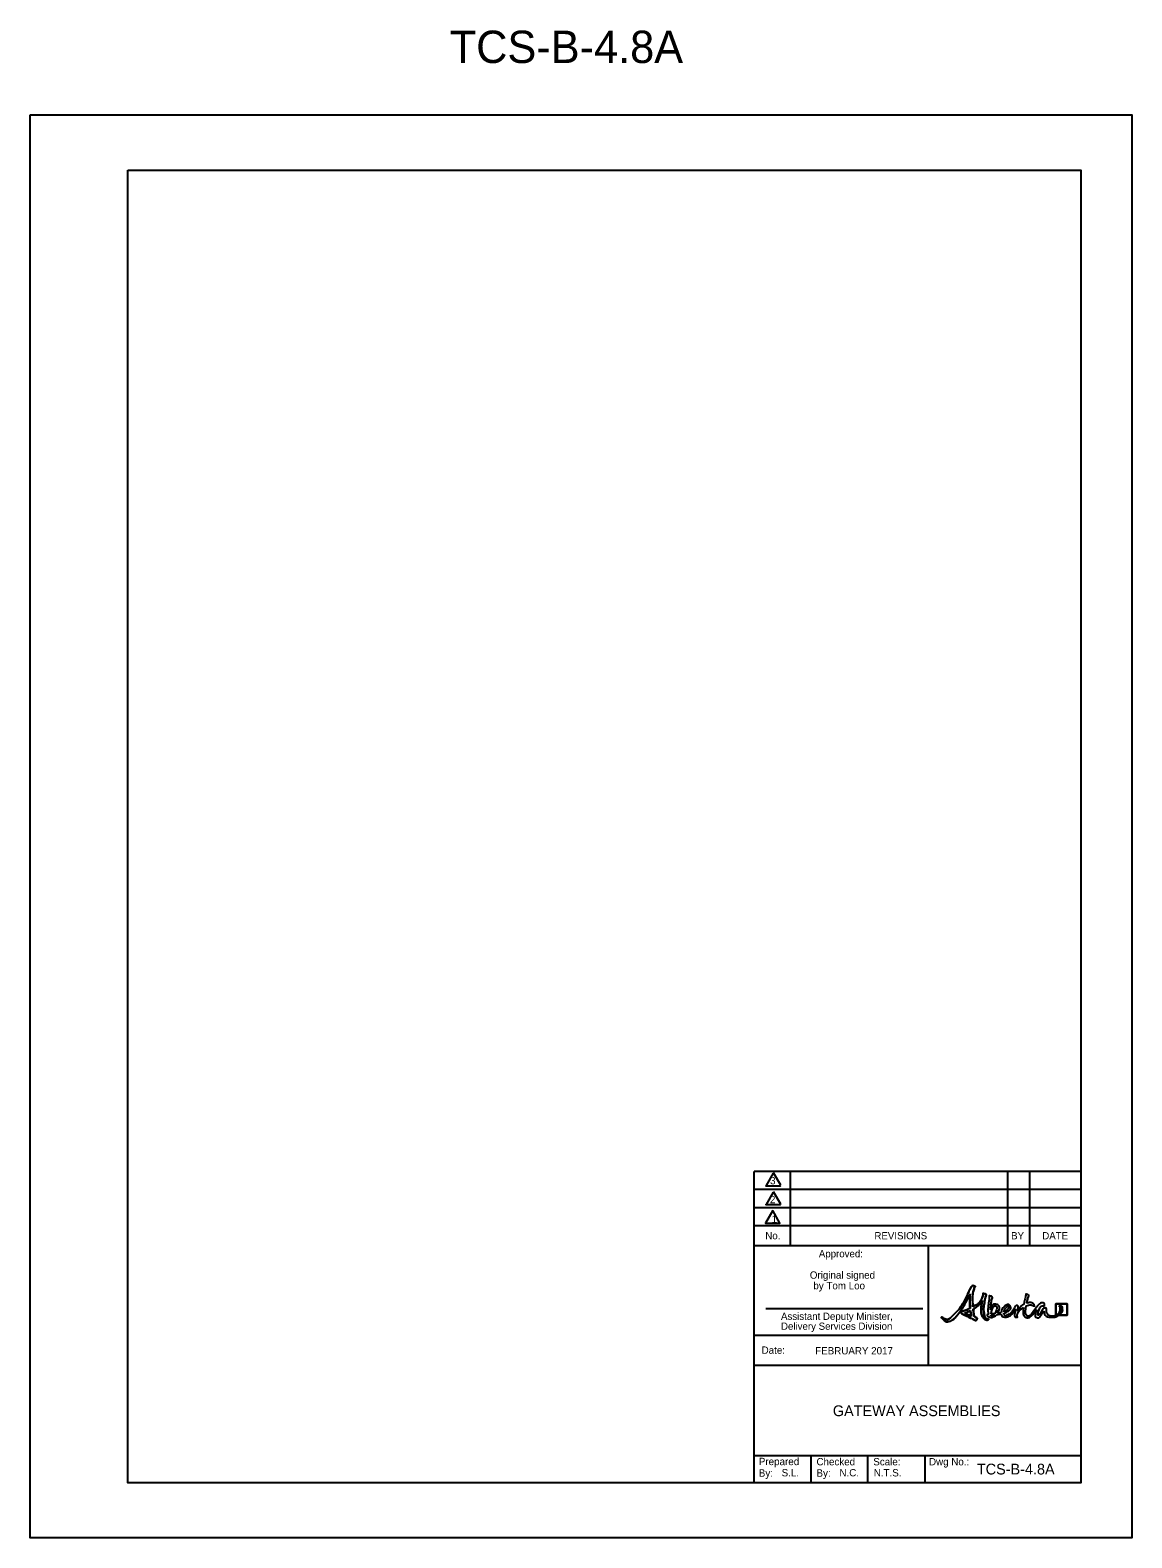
# Model space of a CAD drawing. Extents: x 1535 to 2422, y 125 to 421.
# Drawn here: x 1675.8 to 1891.8, y 125 to 420.6 of the extents above; entities that cross this region are included whole.
import ezdxf

# ---------------------------------------------------------------- set-up
doc = ezdxf.new("R2010")
doc.units = 0
for name, color, linetype in [('Level 1', 7, 'Continuous'), ('Level 10', 7, 'Continuous'), ('Level 2', 7, 'Continuous'), ('Level 22', 7, 'Continuous'), ('Level 44', 7, 'Continuous'), ('Level 53', 7, 'Continuous'), ('Level 60', 7, 'Continuous')]:
    doc.layers.add(name, color=color, linetype=linetype)

msp = doc.modelspace()

# ---------------------------------------------------------------- linework, layer by layer
at = {"layer": 'Level 1'}
for p, q in [((1881.63, 196.82), (1817.75, 196.82)), ((1881.63, 193.27), (1817.75, 193.27)), ((1881.63, 189.72), (1817.75, 189.72)), ((1881.63, 186.18), (1817.75, 186.18)), ((1817.75, 135.79), (1817.75, 182.27)), ((1817.75, 182.27), (1881.63, 182.27)), ((1851.82, 182.27), (1851.82, 158.85)), ((1817.75, 164.71), (1851.82, 164.71)), ((1817.75, 158.85), (1881.63, 158.85)), ((1817.75, 141.11), (1881.63, 141.11)), ((1828.89, 135.79), (1828.89, 141.11)), ((1840.02, 135.79), (1840.02, 141.11)), ((1851.16, 141.11), (1851.16, 135.79))]:
    msp.add_line(p, q, dxfattribs=at)
msp.add_lwpolyline([(1821.37, 189.16), (1819.95, 186.69), (1822.79, 186.69)], close=True, dxfattribs=at)
at = {"layer": 'Level 2'}
msp.add_line((1851.82, 182.27), (1851.82, 182.27), dxfattribs=at)
at = {"layer": 'Level 22'}
msp.add_line((1833.24, 135.79), (1833.24, 135.79), dxfattribs=at)
at = {"layer": 'Level 53'}
msp.add_line((1877.48, 168.64), (1876.93, 168.64), dxfattribs=at)
msp.add_lwpolyline([(1877.48, 168.64), (1879.1, 168.64), (1879.1, 170.87), (1876.87, 170.87), (1876.87, 168.64), (1876.93, 168.64)], dxfattribs=at)
for points, degree in [([(1863.5, 167.83), (1863.26, 167.87), (1862.95, 168.19), (1862.85, 168.73), (1862.68, 169.7), (1862.78, 170.65), (1863.06, 172.07), (1863.12, 172.34), (1863.3, 172.8), (1862.72, 172.89), (1862.53, 172.92), (1862.63, 172.83), (1862.58, 172.59), (1862.35, 171.53), (1861.49, 170.76), (1860.62, 170.25), (1860.53, 171.46), (1860.56, 172.81), (1860.79, 173.64), (1860.98, 174.33), (1861.21, 174.2), (1860.93, 174.35), (1860.63, 174.5), (1860.31, 174.3), (1860.05, 173.78), (1859.79, 173.26), (1858.59, 170.45), (1856.68, 168.55), (1855.7, 167.57), (1854.82, 168.08), (1854.64, 168.22), (1854.5, 168.35), (1854.44, 168.16), (1854.62, 167.97), (1855.41, 167.11), (1856.57, 167.6), (1856.99, 168.02), (1858.15, 169.19), (1859.51, 171.69), (1860.05, 172.75), (1860, 172.15), (1859.99, 171.15), (1860.1, 169.97), (1859.5, 169.69), (1858.97, 169.52), (1858.72, 169.45), (1858.45, 169.38), (1858.28, 169.27), (1858.28, 169.14), (1858.27, 169.01), (1858.46, 168.89), (1858.72, 168.77), (1859.19, 168.54), (1860.56, 167.89), (1860.9, 167.7), (1861.19, 167.53), (1861.33, 167.66), (1861.41, 167.84), (1861.53, 168.08), (1861.22, 168.22), (1860.92, 168.3), (1860.81, 168.7), (1860.72, 169.24), (1860.66, 169.83), (1861.35, 170.26), (1862.04, 170.83), (1862.43, 171.54), (1862.34, 170.95), (1862.08, 168.92), (1862.72, 168.06), (1862.86, 167.87), (1863.17, 167.66), (1863.48, 167.69), (1863.62, 167.71), (1863.69, 167.8), (1863.68, 167.83), (1863.66, 167.86), (1863.58, 167.82), (1863.5, 167.83)], 3), ([(1860.62, 170.25), (1860.53, 171.46), (1860.56, 172.81), (1860.79, 173.64), (1860.98, 174.33), (1861.21, 174.2), (1860.93, 174.35), (1860.63, 174.5), (1860.31, 174.3), (1860.05, 173.78), (1859.79, 173.26), (1858.59, 170.45), (1856.68, 168.55), (1855.7, 167.57), (1854.82, 168.08), (1854.64, 168.22), (1854.5, 168.35), (1854.44, 168.16), (1854.62, 167.97), (1855.41, 167.11), (1856.57, 167.6), (1856.99, 168.02), (1858.15, 169.19), (1859.51, 171.69), (1860.05, 172.75)], 3), ([(1860.05, 172.75), (1860, 172.15), (1859.99, 171.15), (1860.1, 169.97)], 2), ([(1863.5, 167.83), (1863.26, 167.87), (1862.95, 168.19), (1862.85, 168.73), (1862.68, 169.7), (1862.78, 170.65), (1863.06, 172.07), (1863.12, 172.34), (1863.3, 172.8), (1862.72, 172.89), (1862.53, 172.92), (1862.63, 172.83), (1862.58, 172.59), (1862.35, 171.53), (1861.49, 170.76), (1860.62, 170.25)], 3), ([(1860.66, 169.83), (1861.35, 170.26), (1862.04, 170.83), (1862.43, 171.54)], 2), ([(1862.43, 171.54), (1862.34, 170.95), (1862.08, 168.92), (1862.72, 168.06), (1862.86, 167.87), (1863.17, 167.66), (1863.48, 167.69), (1863.62, 167.71), (1863.69, 167.8), (1863.68, 167.83), (1863.66, 167.86), (1863.58, 167.82), (1863.5, 167.83)], 3), ([(1864.04, 169.67), (1864.08, 170.24), (1864.17, 170.93), (1864.3, 171.58), (1864.35, 171.84), (1864.54, 172.31), (1863.95, 172.4), (1863.77, 172.43), (1863.8, 172.34), (1863.81, 172.09), (1863.83, 171.75), (1863.46, 169.71), (1863.66, 168.82)], 3), ([(1871.19, 171.01), (1871.25, 171.31), (1871.33, 171.61), (1871.41, 171.91), (1871.49, 172.17), (1871.71, 172.64), (1871.13, 172.73), (1870.95, 172.76), (1871.03, 172.67), (1870.97, 172.42), (1870.85, 171.96), (1870.71, 171.37), (1870.61, 170.78)], 3), ([(1860.1, 169.97), (1859.5, 169.69), (1858.97, 169.52), (1858.72, 169.45), (1858.45, 169.38), (1858.28, 169.27), (1858.28, 169.14), (1858.27, 169.01), (1858.46, 168.89), (1858.72, 168.77), (1859.19, 168.54), (1860.56, 167.89), (1860.9, 167.7), (1861.19, 167.53), (1861.33, 167.66), (1861.41, 167.84), (1861.53, 168.08), (1861.22, 168.22), (1860.92, 168.3)], 3), ([(1859.03, 169.04), (1859.34, 169.15), (1859.73, 169.32), (1860.14, 169.54)], 2), ([(1859.03, 169.04), (1859.34, 169.15), (1859.73, 169.32), (1860.14, 169.54), (1860.2, 169.06), (1860.26, 168.72), (1860.33, 168.47), (1860.02, 168.58), (1859.59, 168.75), (1859.03, 169.04)], 3), ([(1860.33, 168.47), (1860.02, 168.58), (1859.59, 168.75), (1859.03, 169.04)], 2), ([(1860.14, 169.54), (1860.2, 169.06), (1860.26, 168.72), (1860.33, 168.47)], 2), ([(1860.92, 168.3), (1860.81, 168.7), (1860.72, 169.24), (1860.66, 169.83)], 2), ([(1863.66, 168.82), (1863.4, 168.74), (1863.3, 168.55), (1863.63, 168.35), (1863.85, 168.21), (1864.34, 168.17), (1864.83, 168.41), (1865.01, 168.5), (1865.16, 168.62), (1865.29, 168.77)], 3), ([(1865.47, 169.01), (1865.89, 169.68), (1865.85, 170.59), (1865.25, 170.75), (1864.54, 170.92), (1864.19, 170.24), (1864.04, 169.67)], 3), ([(1864.11, 168.45), (1864.14, 168.48), (1864.16, 168.52), (1864.16, 168.56), (1864.16, 168.59), (1864.16, 168.63), (1864.17, 168.66)], 3), ([(1864.17, 168.66), (1864.29, 168.66), (1864.49, 168.68), (1864.72, 168.7)], 2), ([(1864.19, 168.88), (1864.28, 169.6), (1864.65, 170.59), (1865.12, 170.43), (1865.38, 170.34), (1865.24, 169.5), (1864.9, 168.94)], 3), ([(1864.9, 168.94), (1864.68, 168.92), (1864.44, 168.9), (1864.19, 168.88)], 2), ([(1864.72, 168.7), (1864.6, 168.57), (1864.46, 168.47), (1864.31, 168.45)], 2), ([(1865.29, 168.77), (1865.59, 168.8), (1865.9, 168.85), (1866.18, 168.91)], 2), ([(1866.17, 169.13), (1865.97, 169.08), (1865.74, 169.05), (1865.47, 169.01)], 2), ([(1866.7, 169.03), (1866.8, 169.06), (1866.88, 169.09), (1866.95, 169.13), (1867.84, 169.52), (1868.14, 170.11), (1867.92, 170.47), (1867.7, 170.81), (1867.09, 170.7), (1866.61, 170.2), (1866.38, 169.95), (1866.19, 169.52), (1866.17, 169.13)], 3), ([(1866.18, 168.91), (1866.23, 168.51), (1866.48, 168.21), (1867.08, 168.27), (1867.93, 168.35), (1868.68, 169.39), (1868.96, 169.89)], 3), ([(1869.37, 169.45), (1869.43, 169.72), (1869.52, 170.03), (1869.52, 170.24), (1869.53, 170.45), (1869.38, 170.5), (1869.32, 170.52), (1869.2, 170.55), (1869.04, 170.49), (1868.89, 170.28), (1868.54, 169.78), (1868.09, 168.99), (1867.41, 168.66), (1866.93, 168.43), (1866.71, 168.67), (1866.7, 169.03)], 3), ([(1867.17, 170.15), (1867.47, 170.43), (1867.61, 170.41), (1867.65, 170.33), (1867.74, 170.17), (1867.39, 169.61), (1866.72, 169.3)], 3), ([(1866.72, 169.3), (1866.78, 169.61), (1866.94, 169.94), (1867.17, 170.15)], 2), ([(1868.96, 169.89), (1868.91, 169.35), (1868.56, 168.18), (1869.16, 168.24), (1869.39, 168.26), (1869.29, 168.3), (1869.3, 168.5), (1869.35, 169.21), (1869.94, 169.81), (1870.52, 170.17)], 3), ([(1870.61, 170.78), (1870.14, 170.5), (1869.7, 170.05), (1869.37, 169.45)], 2), ([(1870.52, 170.17), (1870.42, 169.31), (1870.46, 168.54), (1870.85, 168.29), (1871.57, 167.84), (1872.6, 169.03), (1873.16, 169.75)], 3), ([(1876.24, 168.44), (1875.33, 168.44), (1875.09, 169.15), (1875.05, 169.51), (1875.02, 169.74), (1875.07, 170.08), (1874.67, 170.03), (1874.38, 170), (1874.13, 169.45), (1873.77, 168.99), (1873.46, 168.59), (1873.32, 168.63), (1873.39, 168.97), (1873.48, 169.4), (1873.84, 170.4), (1874.25, 170.47), (1874.44, 170.51), (1874.51, 170.18), (1874.59, 170.38), (1874.68, 170.59), (1874.6, 171.04), (1874.18, 171.04), (1873.88, 171.04), (1873.52, 170.73), (1873.23, 170.37), (1872.98, 170.06), (1871.69, 168.17), (1871.15, 168.57), (1870.9, 168.77), (1870.92, 169.54), (1871.08, 170.46)], 3), ([(1871.08, 170.46), (1871.72, 170.71), (1872.25, 170.62), (1872.55, 170.48), (1872.7, 170.41), (1872.72, 170.42), (1872.66, 170.58), (1872.57, 170.82), (1872.05, 171.2), (1871.25, 171.03), (1871.23, 171.02), (1871.21, 171.02), (1871.19, 171.01)], 3), ([(1873.16, 169.75), (1872.87, 169.11), (1872.71, 168.28), (1873.14, 168.16), (1873.64, 168.01), (1874.04, 168.85), (1874.51, 169.49)], 3), ([(1874.51, 169.49), (1874.56, 169.03), (1874.87, 168.23), (1876.11, 168.23), (1876.66, 168.23), (1877.13, 168.39), (1877.48, 168.64)], 3), ([(1876.93, 168.64), (1876.73, 168.52), (1876.49, 168.44), (1876.24, 168.44)], 2), ([(1876.87, 170.87), (1876.87, 170.87), (1876.87, 168.64), (1876.87, 168.64), (1876.87, 168.64), (1876.93, 168.64), (1876.93, 168.64), (1877.42, 168.93), (1877.74, 169.48), (1877.74, 169.94), (1877.74, 170.33), (1877.53, 170.31), (1877.56, 170.37), (1877.63, 170.53), (1878.12, 170.44), (1878.15, 169.88), (1878.17, 169.41), (1877.92, 168.95), (1877.48, 168.64), (1877.48, 168.64), (1879.1, 168.64), (1879.1, 168.64), (1879.1, 168.64), (1879.1, 170.87), (1879.1, 170.87), (1879.1, 170.87), (1876.87, 170.87), (1876.87, 170.87)], 3), ([(1876.93, 168.64), (1877.42, 168.93), (1877.74, 169.48), (1877.74, 169.94), (1877.74, 170.33), (1877.53, 170.31), (1877.56, 170.37), (1877.63, 170.53), (1878.12, 170.44), (1878.15, 169.88), (1878.17, 169.41), (1877.92, 168.95), (1877.48, 168.64)], 3), ([(1864.31, 168.45), (1864.23, 168.44), (1864.16, 168.44), (1864.11, 168.45)], 2)]:
    msp.add_open_spline(points, degree=degree, dxfattribs=at)
at = {"layer": 'Level 60'}
for p, q in [((1675.78, 403.98), (1675.78, 403.98)), ((1817.75, 190.35), (1817.75, 196.82)), ((1824.84, 190.35), (1824.84, 196.82)), ((1867.43, 196.82), (1867.43, 182.27)), ((1871.74, 196.82), (1871.74, 182.27)), ((1817.75, 182.27), (1817.75, 190.35)), ((1824.84, 182.27), (1824.84, 190.35)), ((1820.01, 169.95), (1850.83, 169.95)), ((1891.78, 124.98), (1891.78, 124.98))]:
    msp.add_line(p, q, dxfattribs=at)
for points in [[(1675.78, 403.98), (1891.78, 403.98), (1891.78, 124.98), (1675.78, 124.98)], [(1694.9, 393.17), (1881.78, 393.17), (1881.78, 135.79), (1694.9, 135.79)]]:
    msp.add_lwpolyline(points, close=True, dxfattribs=at)
for points in [[(1821.45, 196.49), (1820.06, 194.07)], [(1822.93, 194.14), (1821.54, 196.57)], [(1820.06, 194.07), (1820.03, 194.02), (1822.87, 194.02), (1822.85, 194.07)], [(1821.45, 192.78), (1820.06, 190.35)], [(1822.93, 190.43), (1821.54, 192.85)], [(1820.06, 190.35), (1820.03, 190.31), (1822.87, 190.31), (1822.85, 190.35)]]:
    msp.add_lwpolyline(points, dxfattribs=at)

# ---------------------------------------------------------------- texts
at = {"layer": 'Level 1'}
for s, height, p in [('3', 1.45, (1820.84, 194.29)), ('2', 1.45, (1820.82, 190.58)), ('1', 1.45, (1821.15, 186.75)), ('No.', 1.419, (1819.92, 183.51)), ('REVISIONS', 1.419, (1841.31, 183.51)), ('BY', 1.419, (1868.11, 183.51)), ('DATE', 1.419, (1874.22, 183.51)), ('Date:', 1.434, (1819.19, 161.07)), ('Prepared', 1.441, (1818.64, 139.23)), ('Checked', 1.434, (1829.95, 139.19)), ('Scale:', 1.434, (1841.09, 139.19)), ('Dwg No.:', 1.434, (1852.01, 139.19)), ('By:', 1.441, (1818.64, 136.97)), ('By:', 1.441, (1829.95, 136.97)), ('    N.T.S.   ', 1.4336, (1839.06, 137.02))]:
    msp.add_text(s, height=height, rotation=360, dxfattribs=at).set_placement(p)
at = {"layer": 'Level 10'}
msp.add_text('GATEWAY ASSEMBLIES', height=2.116, rotation=360, dxfattribs=at).set_placement((1833.16, 148.84))
at = {"layer": 'Level 44'}
msp.add_text('TCS-B-4.8A', height=6.348, rotation=360, dxfattribs=at).set_placement((1758.04, 414.16))
at = {"layer": 'Level 60'}
for s, height, p in [('Approved:', 1.419, (1830.41, 179.98)), ('Original signed', 1.434, (1828.64, 175.79)), ('by Tom Loo', 1.434, (1829.34, 173.71)), ('Assistant Deputy Minister,', 1.4194, (1822.99, 167.72)), ('Delivery Services Division', 1.4194, (1822.99, 165.77)), ('FEBRUARY 2017', 1.434, (1829.7, 160.95)), ('TCS-B-4.8A', 2.116, (1861.39, 137.4))]:
    msp.add_text(s, height=height, dxfattribs=at).set_placement(p)
for s, p in [('S.L.', (1823.12, 137.03)), ('N.C.', (1834.45, 137.03))]:
    msp.add_text(s, height=1.434, rotation=360, dxfattribs=at).set_placement(p)

doc.saveas('drawing.dxf')
